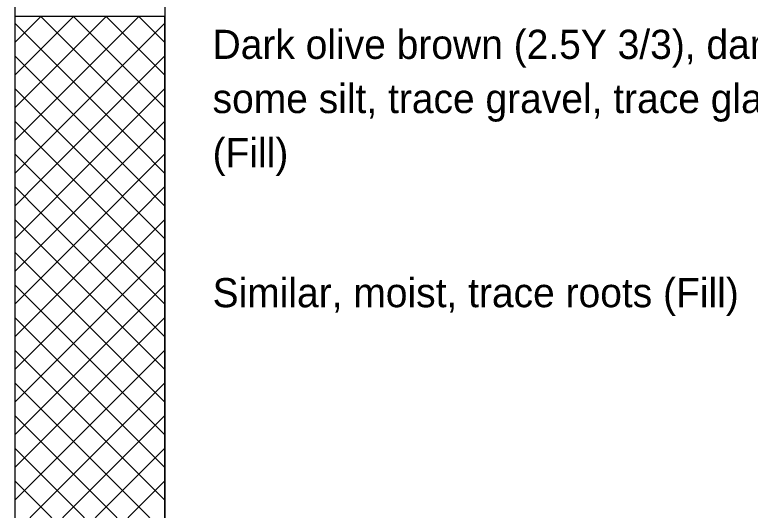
# Model space of a CAD drawing. Extents: x 9419 to 9552, y 6780 to 6865.
# Drawn here: x 9514.02 to 9519.65, y 6843.19 to 6846.98 of the extents above; entities that cross this region are included whole.
import ezdxf

# ---------------------------------------------------------------- set-up
doc = ezdxf.new("R2010")
doc.units = 0
doc.layers.add('7', color=7, linetype='Continuous')
doc.layers.add('8', color=7, linetype='Continuous')

msp = doc.modelspace()

# ---------------------------------------------------------------- linework, layer by layer
at = {"layer": '7'}
for p, q in [((9514.0232, 6846.9683), (9514.0232, 6842.9684)), ((9515.1715, 6846.9683), (9514.0232, 6846.9683)), ((9515.1715, 6842.9684), (9515.1715, 6846.9683))]:
    msp.add_line(p, q, dxfattribs=at)
for points in [[(9514.0232, 6850.4861), (9514.0232, 6821.9406)], [(9515.1715, 6850.4861), (9515.1715, 6821.9406)]]:
    msp.add_lwpolyline(points, dxfattribs=at)
at = {"layer": '8'}
for p, q in [((9514.0232, 6846.7692), (9514.2223, 6846.9683)), ((9514.4723, 6846.7183), (9514.2223, 6846.9683)), ((9514.2223, 6846.7183), (9514.4723, 6846.9683)), ((9514.7223, 6846.7183), (9514.4723, 6846.9683)), ((9514.4723, 6846.7183), (9514.7223, 6846.9683)), ((9514.9723, 6846.7183), (9514.7223, 6846.9683)), ((9514.7223, 6846.7183), (9514.9723, 6846.9683)), ((9515.1715, 6846.7692), (9514.9723, 6846.9683)), ((9514.2223, 6846.7183), (9514.0232, 6846.9175)), ((9514.9723, 6846.7183), (9515.1715, 6846.9175)), ((9514.0232, 6846.5192), (9514.2223, 6846.7183)), ((9514.2223, 6846.4683), (9514.0232, 6846.6675)), ((9514.4723, 6846.4683), (9514.2223, 6846.7183)), ((9514.2223, 6846.4683), (9514.4723, 6846.7183)), ((9514.7223, 6846.4683), (9514.4723, 6846.7183)), ((9514.4723, 6846.4683), (9514.7223, 6846.7183)), ((9514.9723, 6846.4683), (9514.7223, 6846.7183)), ((9514.7223, 6846.4683), (9514.9723, 6846.7183)), ((9515.1715, 6846.5192), (9514.9723, 6846.7183)), ((9514.9723, 6846.4683), (9515.1715, 6846.6675)), ((9514.0232, 6846.2692), (9514.2223, 6846.4683)), ((9514.4723, 6846.2183), (9514.2223, 6846.4683)), ((9514.2223, 6846.2183), (9514.4723, 6846.4683)), ((9514.7223, 6846.2183), (9514.4723, 6846.4683)), ((9514.4723, 6846.2183), (9514.7223, 6846.4683)), ((9514.9723, 6846.2183), (9514.7223, 6846.4683)), ((9514.7223, 6846.2183), (9514.9723, 6846.4683)), ((9515.1715, 6846.2692), (9514.9723, 6846.4683)), ((9514.2223, 6846.2183), (9514.0232, 6846.4175)), ((9514.9723, 6846.2183), (9515.1715, 6846.4175)), ((9514.0232, 6846.0192), (9514.2223, 6846.2183)), ((9514.4723, 6845.9683), (9514.2223, 6846.2183)), ((9514.2223, 6845.9683), (9514.4723, 6846.2183)), ((9514.7223, 6845.9683), (9514.4723, 6846.2183)), ((9514.4723, 6845.9683), (9514.7223, 6846.2183)), ((9514.9723, 6845.9683), (9514.7223, 6846.2183)), ((9514.7223, 6845.9683), (9514.9723, 6846.2183)), ((9515.1715, 6846.0192), (9514.9723, 6846.2183)), ((9514.2223, 6845.9683), (9514.0232, 6846.1675)), ((9514.9723, 6845.9683), (9515.1715, 6846.1675)), ((9514.0232, 6845.7692), (9514.2223, 6845.9683)), ((9514.4723, 6845.7184), (9514.2223, 6845.9683)), ((9514.2223, 6845.7184), (9514.4723, 6845.9683)), ((9514.7223, 6845.7184), (9514.4723, 6845.9683)), ((9514.4723, 6845.7184), (9514.7223, 6845.9683)), ((9514.9723, 6845.7184), (9514.7223, 6845.9683)), ((9514.7223, 6845.7184), (9514.9723, 6845.9683)), ((9515.1715, 6845.7692), (9514.9723, 6845.9683)), ((9514.2223, 6845.7184), (9514.0232, 6845.9175)), ((9514.9723, 6845.7184), (9515.1715, 6845.9175)), ((9514.0232, 6845.5192), (9514.2223, 6845.7184)), ((9514.4723, 6845.4683), (9514.2223, 6845.7184)), ((9514.2223, 6845.4683), (9514.4723, 6845.7184)), ((9514.7223, 6845.4683), (9514.4723, 6845.7184)), ((9514.4723, 6845.4683), (9514.7223, 6845.7184)), ((9514.9723, 6845.4683), (9514.7223, 6845.7184)), ((9514.7223, 6845.4683), (9514.9723, 6845.7184)), ((9515.1715, 6845.5192), (9514.9723, 6845.7184)), ((9514.2223, 6845.4683), (9514.0232, 6845.6675)), ((9514.9723, 6845.4683), (9515.1715, 6845.6675)), ((9514.0232, 6845.2692), (9514.2223, 6845.4683)), ((9514.4723, 6845.2184), (9514.2223, 6845.4683)), ((9514.2223, 6845.2184), (9514.4723, 6845.4683)), ((9514.7223, 6845.2184), (9514.4723, 6845.4683)), ((9514.4723, 6845.2184), (9514.7223, 6845.4683)), ((9514.9723, 6845.2184), (9514.7223, 6845.4683)), ((9514.7223, 6845.2184), (9514.9723, 6845.4683)), ((9515.1715, 6845.2692), (9514.9723, 6845.4683)), ((9514.2223, 6845.2184), (9514.0232, 6845.4175)), ((9514.9723, 6845.2184), (9515.1715, 6845.4175)), ((9514.0232, 6845.0192), (9514.2223, 6845.2184)), ((9514.4723, 6844.9684), (9514.2223, 6845.2184)), ((9514.2223, 6844.9684), (9514.4723, 6845.2184)), ((9514.7223, 6844.9684), (9514.4723, 6845.2184)), ((9514.4723, 6844.9684), (9514.7223, 6845.2184)), ((9514.9723, 6844.9684), (9514.7223, 6845.2184)), ((9514.7223, 6844.9684), (9514.9723, 6845.2184)), ((9515.1715, 6845.0192), (9514.9723, 6845.2184)), ((9514.2223, 6844.9684), (9514.0232, 6845.1675)), ((9514.9723, 6844.9684), (9515.1715, 6845.1675)), ((9514.0232, 6844.7692), (9514.2223, 6844.9684)), ((9514.4723, 6844.7184), (9514.2223, 6844.9684)), ((9514.2223, 6844.7184), (9514.4723, 6844.9684)), ((9514.7223, 6844.7184), (9514.4723, 6844.9684)), ((9514.4723, 6844.7184), (9514.7223, 6844.9684)), ((9514.9723, 6844.7184), (9514.7223, 6844.9684)), ((9514.7223, 6844.7184), (9514.9723, 6844.9684)), ((9515.1715, 6844.7692), (9514.9723, 6844.9684)), ((9514.2223, 6844.7184), (9514.0232, 6844.9175)), ((9514.9723, 6844.7184), (9515.1715, 6844.9175)), ((9514.0232, 6844.5192), (9514.2223, 6844.7184)), ((9514.4723, 6844.4684), (9514.2223, 6844.7184)), ((9514.2223, 6844.4684), (9514.4723, 6844.7184)), ((9514.7223, 6844.4684), (9514.4723, 6844.7184)), ((9514.4723, 6844.4684), (9514.7223, 6844.7184)), ((9514.9723, 6844.4684), (9514.7223, 6844.7184)), ((9514.7223, 6844.4684), (9514.9723, 6844.7184)), ((9515.1715, 6844.5192), (9514.9723, 6844.7184)), ((9514.2223, 6844.4684), (9514.0232, 6844.6675)), ((9514.9723, 6844.4684), (9515.1715, 6844.6675)), ((9514.0232, 6844.2692), (9514.2223, 6844.4684)), ((9514.4723, 6844.2184), (9514.2223, 6844.4684)), ((9514.2223, 6844.2184), (9514.4723, 6844.4684)), ((9514.7223, 6844.2184), (9514.4723, 6844.4684)), ((9514.4723, 6844.2184), (9514.7223, 6844.4684)), ((9514.9723, 6844.2184), (9514.7223, 6844.4684)), ((9514.7223, 6844.2184), (9514.9723, 6844.4684)), ((9515.1715, 6844.2692), (9514.9723, 6844.4684)), ((9514.2223, 6844.2184), (9514.0232, 6844.4175)), ((9514.9723, 6844.2184), (9515.1715, 6844.4175)), ((9514.0232, 6844.0192), (9514.2223, 6844.2184)), ((9514.4723, 6843.9684), (9514.2223, 6844.2184)), ((9514.2223, 6843.9684), (9514.4723, 6844.2184)), ((9514.7223, 6843.9684), (9514.4723, 6844.2184)), ((9514.4723, 6843.9684), (9514.7223, 6844.2184)), ((9514.9723, 6843.9684), (9514.7223, 6844.2184)), ((9514.7223, 6843.9684), (9514.9723, 6844.2184)), ((9515.1715, 6844.0192), (9514.9723, 6844.2184)), ((9514.2223, 6843.9684), (9514.0232, 6844.1675)), ((9514.9723, 6843.9684), (9515.1715, 6844.1675)), ((9514.0232, 6843.7692), (9514.2223, 6843.9684)), ((9514.4723, 6843.7184), (9514.2223, 6843.9684)), ((9514.2223, 6843.7184), (9514.4723, 6843.9684)), ((9514.7223, 6843.7184), (9514.4723, 6843.9684)), ((9514.4723, 6843.7184), (9514.7223, 6843.9684)), ((9514.9723, 6843.7184), (9514.7223, 6843.9684)), ((9514.7223, 6843.7184), (9514.9723, 6843.9684)), ((9515.1715, 6843.7692), (9514.9723, 6843.9684)), ((9514.2223, 6843.7184), (9514.0232, 6843.9175)), ((9514.9723, 6843.7184), (9515.1715, 6843.9175)), ((9514.0232, 6843.5192), (9514.2223, 6843.7184)), ((9514.4723, 6843.4684), (9514.2223, 6843.7184)), ((9514.2223, 6843.4684), (9514.4723, 6843.7184)), ((9514.7223, 6843.4684), (9514.4723, 6843.7184)), ((9514.4723, 6843.4684), (9514.7223, 6843.7184)), ((9514.9723, 6843.4684), (9514.7223, 6843.7184)), ((9514.7223, 6843.4684), (9514.9723, 6843.7184)), ((9515.1715, 6843.5192), (9514.9723, 6843.7184)), ((9514.2223, 6843.4684), (9514.0232, 6843.6675)), ((9514.9723, 6843.4684), (9515.1715, 6843.6675)), ((9514.0232, 6843.2692), (9514.2223, 6843.4684)), ((9514.4723, 6843.2184), (9514.2223, 6843.4684)), ((9514.2223, 6843.2184), (9514.4723, 6843.4684)), ((9514.7223, 6843.2184), (9514.4723, 6843.4684)), ((9514.4723, 6843.2184), (9514.7223, 6843.4684)), ((9514.9723, 6843.2184), (9514.7223, 6843.4684)), ((9514.7223, 6843.2184), (9514.9723, 6843.4684)), ((9515.1715, 6843.2692), (9514.9723, 6843.4684)), ((9514.2223, 6843.2184), (9514.0232, 6843.4175)), ((9514.9723, 6843.2184), (9515.1715, 6843.4175)), ((9514.0232, 6843.0192), (9514.2223, 6843.2184)), ((9514.4723, 6842.9684), (9514.2223, 6843.2184)), ((9514.2223, 6842.9684), (9514.4723, 6843.2184)), ((9514.7223, 6842.9684), (9514.4723, 6843.2184)), ((9514.4723, 6842.9684), (9514.7223, 6843.2184)), ((9514.9723, 6842.9684), (9514.7223, 6843.2184)), ((9514.7223, 6842.9684), (9514.9723, 6843.2184)), ((9515.1715, 6843.0192), (9514.9723, 6843.2184))]:
    msp.add_line(p, q, dxfattribs=at)

# ---------------------------------------------------------------- texts
at = {"layer": '7'}
for s, p in [('Dark olive brown (2.5Y 3/3), damp,  medium dense, SAND,', (9515.536, 6846.6443)), ('some silt, trace gravel, trace glass, poorly-graded', (9515.536, 6846.23)), ('(Fill)', (9515.536, 6845.8158)), ('Similar, moist, trace roots (Fill)', (9515.536, 6844.7456))]:
    msp.add_text(s, height=0.2228, dxfattribs=at).set_placement(p)

doc.saveas('drawing.dxf')
